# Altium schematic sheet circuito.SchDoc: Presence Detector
size A4; Date: 2/11/2014; CheckedBy: Óscar Ramón Adamuz Hinojosa; Author: Óscar Ramón Adamuz Hinojosa; DrawnBy: Óscar Ramón Adamuz HInojosa; Engineer: Óscar Ramón Adamuz Hinojosa; DocumentNumber: v2.0; SheetNumber: v2.0
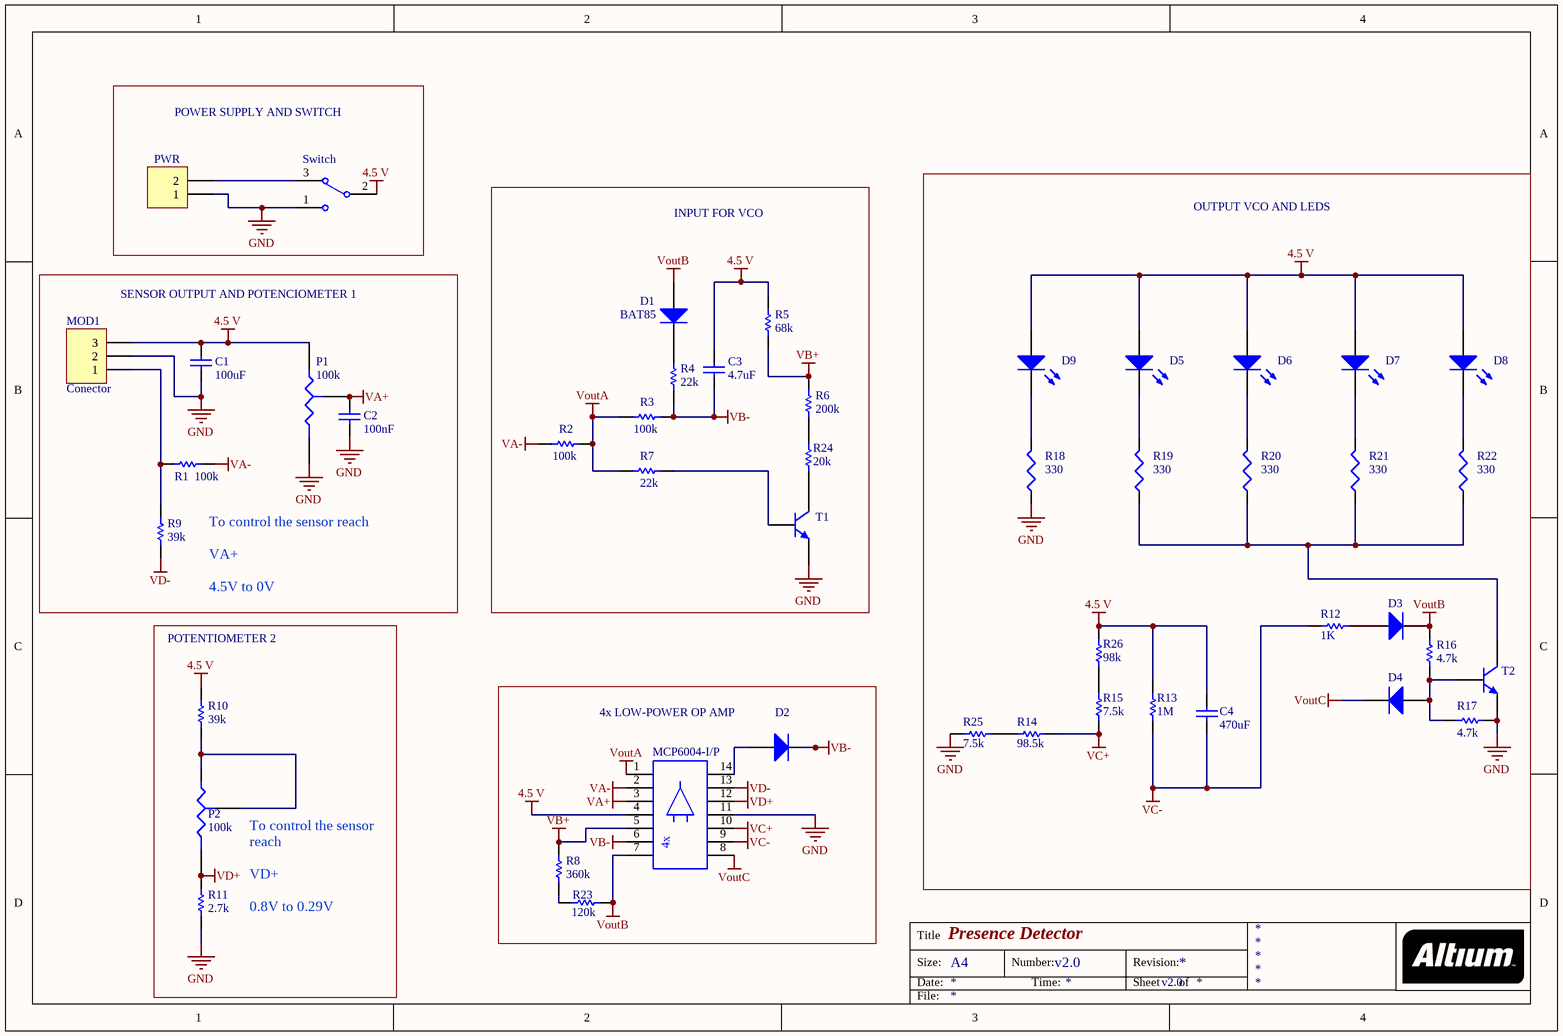
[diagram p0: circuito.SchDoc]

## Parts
C1  value 100uF  [Condensador 5mm]  (hidden comment: Cap)
C2  value 100nF  [Condensador 5mm]  (hidden comment: Cap)
C3  value 4.7uF  [Condensador 5mm]  (hidden comment: Cap)
C4  value 470uF  [Condensador 6.3mm]  (hidden comment: Cap)
D1  BAT85  [BAT85]
D2  Diode BAT18  [BAT85]  (value not drawn)
D3  Diode BAT18  [BAT85]  (value not drawn)
D4  Diode BAT18  [BAT85]  (value not drawn)
D5  LED  [LED]  (value not drawn)
D6  LED  [LED]  (value not drawn)
D7  LED  [LED]  (value not drawn)
D8  LED  [LED]  (value not drawn)
D9  LED  [LED verde]  (value not drawn)
MCP6004-I/P  MCP6004-I/P  [MCP6004]  (value not drawn)
MOD1  Conector  [Conector]
P1  value 100k  [POTENCIOMETRO]  (hidden comment: Res Tap)
P2  value 100k  [POTENCIOMETRO]  (hidden comment: Res Tap)
PWR  Header 2  [ALM]  (value not drawn)
R1  value 100k  [SMD 0805]  (hidden comment: Res1)
R2  value 100k  [SMD 0805]  (hidden comment: Res1)
R3  value 100k  [SMD 0805]  (hidden comment: Res1)
R4  value 22k  [SMD 0805]  (hidden comment: Res1)
R5  value 68k  [SMD 0805]  (hidden comment: Res1)
R6  value 200k  [SMD 0805]  (hidden comment: Res1)
R7  value 22k  [SMD 0805]  (hidden comment: Res1)
R8  value 360k  [SMD 0603]  (hidden comment: Res1)
R9  value 39k  [SMD 0805]  (hidden comment: Res1)
R10  value 39k  [SMD 0805]  (hidden comment: Res1)
R11  value 2.7k  [SMD 0805]  (hidden comment: Res1)
R12  value 1K  [SMD 0805]  (hidden comment: Res1)
R13  value 1M  [SMD 0805]  (hidden comment: Res1)
R14  value 98.5k  [SMD 0805]  (hidden comment: Res1)
R15  value 7.5k  [SMD 0805]  (hidden comment: Res1)
R16  value 4.7k  [SMD 0805]  (hidden comment: Res1)
R17  value 4.7k  [SMD 0805]  (hidden comment: Res1)
R18  value 330  [SMD 0805]  (hidden comment: Res3)
R19  value 330  [SMD 0805]  (hidden comment: Res3)
R20  value 330  [SMD 0805]  (hidden comment: Res3)
R21  value 330  [SMD 0805]  (hidden comment: Res3)
R22  value 330  [SMD 0805]  (hidden comment: Res3)
R23  value 120k  [SMD 0805]  (hidden comment: Res1)
R24  value 20k  [SMD 0805]  (hidden comment: Resistencia)
R25  value 7.5k  [SMD 0805]  (hidden comment: Resistencia)
R26  value 98k  [SMD 0805]  (hidden comment: Resistencia)
SWC  Switch  [switch]
T1  2N3904  [T1 BC550C]  (value not drawn)
T2  QNPN  [T2 BD139]  (value not drawn)

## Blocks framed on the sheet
POWER SUPPLY AND SWITCH: PWR SWC
INPUT FOR VCO: C3 D1 R2-R7 R24 T1
OUTPUT VCO AND LEDS: C4 D3-D9 R12-R22 R25 R26 T2
SENSOR OUTPUT AND POTENCIOMETER 1: C1 C2 MOD1 P1 R1 R9
POTENTIOMETER 2: P2 R10 R11
4x LOW-POWER OP AMP: D2 MCP6004-I/P R8 R23

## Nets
4.5 V: C1.2 C3.2 C4.2 D5.1(A) D6.1(A) D7.1(A) D8.1(A) D9.1(A) MCP6004-I/P.4(A4) MOD1.3 P1.1(A) R5.2 R10.2 R13.2 R26.2 SWC.2
GND: C1.1 C2.1 MCP6004-I/P.11(B4) MOD1.2 P1.2(B) PWR.2(1) R11.1 R17.2 R18.1 R25.2 SWC.1 T1.3(E) T2.1(E)
VA+: C2.2 MCP6004-I/P.3(A3) P1.3(TAP)
VA-: MCP6004-I/P.2(A2) R1.2 R2.1
VB+: MCP6004-I/P.5(A5) R5.1 R6.2 R8.2
VB-: C3.1 D2.3(K) MCP6004-I/P.6(A6) R3.2 R4.1
VC+: MCP6004-I/P.10(B5) R14.1 R15.1
VC-: C4.1 MCP6004-I/P.9(B6) R12.2 R13.1
VD+: MCP6004-I/P.12(B3) P2.2(B) R11.2
VD-: MCP6004-I/P.13(B2) R9.1
VoutA: MCP6004-I/P.1(A1) R2.2 R3.1 R7.1
VoutB: D1.1(A) D3.3(K) MCP6004-I/P.7(A7) R16.2 R23.1
VoutC: D4.3(K) MCP6004-I/P.8(B7)
NetD1_3: D1.3(K) R4.2
NetD2_1: D2.1(A) MCP6004-I/P.14(B1)
NetD3_1: D3.1(A) R12.1
NetD4_1: D4.1(A) R16.1 R17.1 T2.3(B)
NetD5_2: D5.2(K) R19.2
NetD6_2: D6.2(K) R20.2
NetD7_2: D7.2(K) R21.2
NetD8_2: D8.2(K) R22.2
NetD9_2: D9.2(K) R18.2
NetMOD1_1: MOD1.1 R1.1 R9.2
NetP2_1: P2.1(A) P2.3(TAP) R10.1
NetPWR_1: PWR.1(2) SWC.3
NetR6_1: R6.1 R24.2
NetR7_2: R7.2 T1.2(B)
NetR8_1: R8.1 R23.2
NetR14_2: R14.2 R25.1
NetR15_2: R15.2 R26.1
NetR19_1: R19.1 R20.1 R21.1 R22.1 T2.2(C)
NetR24_1: R24.1 T1.1(C)

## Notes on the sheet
- To control the sensor reach
  VA+
  4.5V to 0V
- To control the sensor reach
  VD+
  0.8V to 0.29V

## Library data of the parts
C1-C4 = Cap: Capacitor
D1-D4 = Diode BAT18: Low-Loss RF Switching Diode; pin to pad: 3>2; Note: Pin 2 is not connected and not drawn.
D5-D9 = LED2: Typical RED, GREEN, YELLOW, AMBER GaAs LED
MCP6004-I/P = MCP6004-I/P: DIP Switch, 7 Position, SPST
MOD1 = Header 3: Header, 3-Pin
P1 = Res Tap: Tapped Resistor; pin to pad: 1>3 2>1 3>2; Sim Note: Enter the Resistance value and the set point into parameter fields.; Set Position: 0.5
P2 = Res Tap: Tapped Resistor; pin to pad: 1>2 2>1; Sim Note: Enter the Resistance value and the set point into parameter fields.; Set Position: 0.5
PWR = Header 2: Header, 2-Pin
R1-R17 R23 = Res1: Resistor
R18-R22 = Res3: Resistor
R24-R26 = Resistencia: Resistor
SWC = Conmutador
T1 = 2N3904: NPN General Purpose Amplifier
T2 = QNPN: NPN Bipolar Transistor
